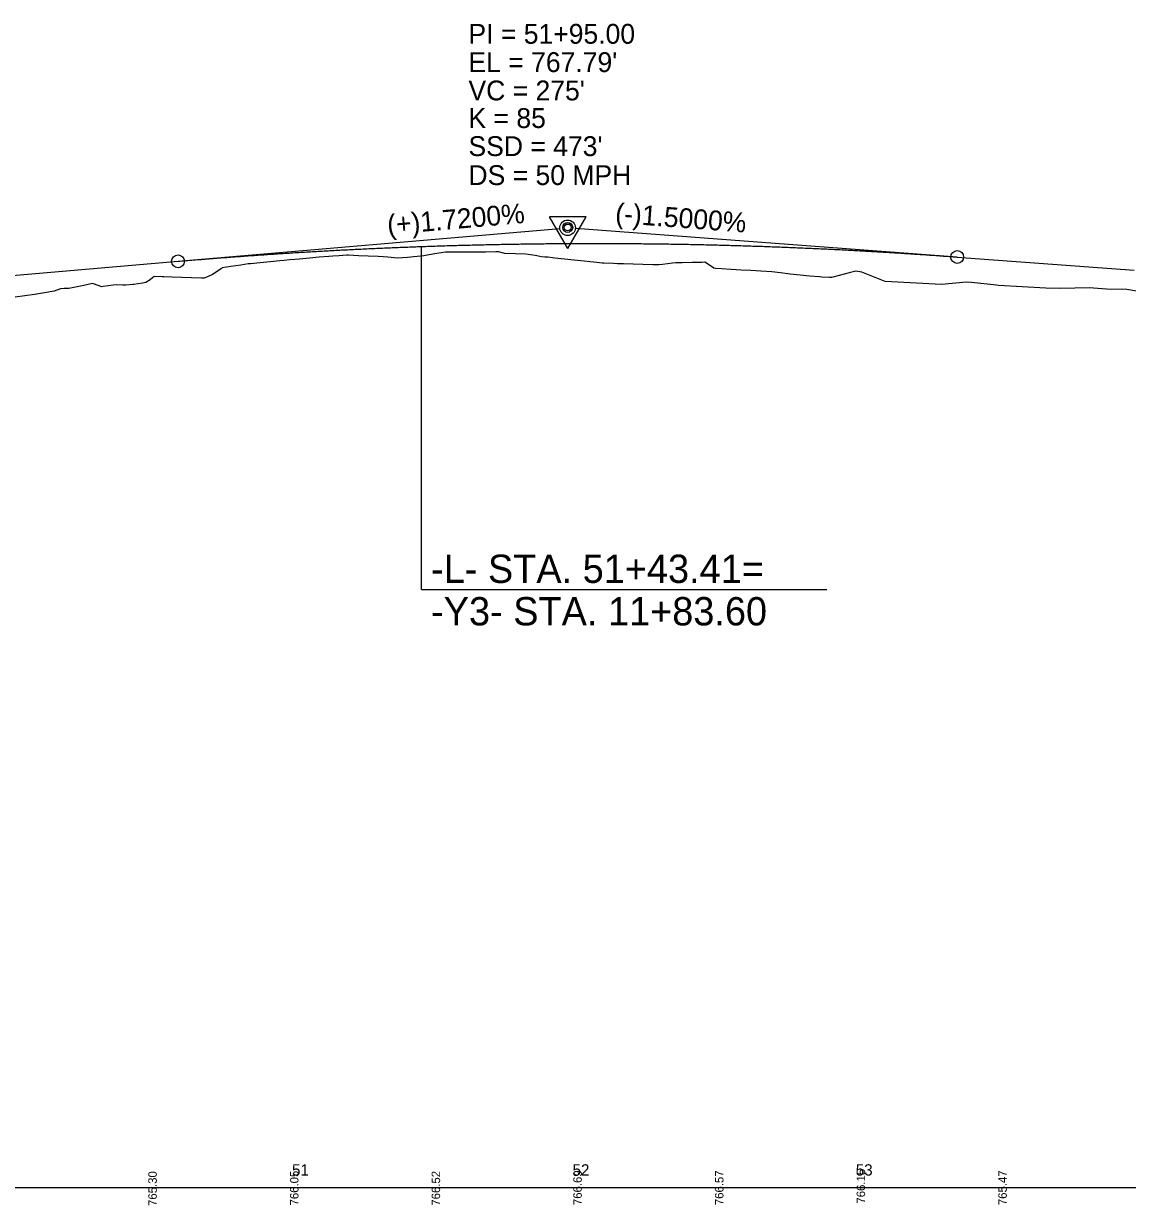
# Model space of a CAD drawing. Extents: x 1554255 to 1803987, y 659549 to 692876.
# Drawn here: x 1558796.7 to 1559186.2, y 692255.6 to 692672.9 of the extents above; entities that cross this region are included whole.
import ezdxf

# ---------------------------------------------------------------- set-up
doc = ezdxf.new("R2010")
doc.units = 0
for name, color, linetype in [('Default', 7, 'Continuous'), ('Exist Profile Cell', 7, 'Continuous'), ('Exist Vertical Profile Ground Line', 7, 'Continuous'), ('Prop PFL Text', 7, 'Continuous'), ('Prop PFL VPI Symbol CELL', 7, 'Continuous'), ('Prop Vertical Profile Curve Label', 7, 'Continuous'), ('Prop Vertical Profile Grade', 7, 'Continuous'), ('Prop Vertical Profile Grade Label', 7, 'Continuous'), ('Prop Vertical Profile Strip Grade', 7, 'Continuous'), ('Prop VPI Label', 7, 'Continuous')]:
    doc.layers.add(name, color=color, linetype=linetype)

msp = doc.modelspace()

# ---------------------------------------------------------------- linework, layer by layer
at = {"layer": 'Exist Profile Cell'}
msp.add_line((1554793.69, 692261.88), (1561762.5, 692261.88), dxfattribs=at)
at = {"layer": 'Exist Vertical Profile Ground Line'}
for p, q in [((1558887.16, 692589.17), (1558883.7, 692588.83)), ((1558888.64, 692589.32), (1558887.16, 692589.17)), ((1558890.62, 692589.5), (1558888.64, 692589.32)), ((1558894.08, 692589.81), (1558890.62, 692589.5)), ((1558897.55, 692590.12), (1558894.08, 692589.81)), ((1558901.01, 692590.43), (1558897.55, 692590.12)), ((1558904.47, 692590.73), (1558901.01, 692590.43)), ((1558905.83, 692590.85), (1558904.47, 692590.73)), ((1558907.94, 692590.98), (1558905.83, 692590.85)), ((1558910.79, 692591.14), (1558907.94, 692590.98)), ((1558911.4, 692591.12), (1558910.79, 692591.14)), ((1558914.86, 692590.97), (1558911.4, 692591.12)), ((1558918.33, 692590.81), (1558914.86, 692590.97)), ((1558921.79, 692590.66), (1558918.33, 692590.81)), ((1558923.59, 692590.58), (1558921.79, 692590.66)), ((1558925.25, 692590.44), (1558923.59, 692590.58)), ((1558928.7, 692590.08), (1558925.25, 692590.44)), ((1558932.18, 692590.4), (1558928.7, 692590.08)), ((1558935.64, 692590.71), (1558932.18, 692590.4)), ((1558937.99, 692590.92), (1558935.64, 692590.71)), ((1558939.11, 692591.12), (1558937.99, 692590.92)), ((1558942.57, 692591.73), (1558939.11, 692591.12)), ((1558945.55, 692592.25), (1558942.57, 692591.73)), ((1558946.03, 692592.25), (1558945.55, 692592.25)), ((1558949.49, 692592.26), (1558946.03, 692592.25)), ((1558952.96, 692592.27), (1558949.49, 692592.26)), ((1558956.42, 692592.27), (1558952.96, 692592.27)), ((1558959.88, 692592.28), (1558956.42, 692592.27)), ((1558963.35, 692592.29), (1558959.88, 692592.28)), ((1558964.32, 692592.29), (1558963.35, 692592.29)), ((1558966.56, 692591.77), (1558964.32, 692592.29)), ((1558970.27, 692591.67), (1558966.56, 692591.77)), ((1558973.97, 692591.57), (1558970.27, 692591.67)), ((1558977.2, 692591.02), (1558973.97, 692591.57)), ((1558979.45, 692590.63), (1558977.2, 692591.02)), ((1558980.66, 692590.52), (1558979.45, 692590.63)), ((1558981.7, 692590.43), (1558980.66, 692590.52)), ((1558984.13, 692590.16), (1558981.7, 692590.43)), ((1558987.59, 692589.78), (1558984.13, 692590.16)), ((1558991.05, 692589.39), (1558987.59, 692589.78)), ((1558994.51, 692589.01), (1558991.05, 692589.39)), ((1558996.55, 692588.79), (1558994.51, 692589.01)), ((1558866.38, 692586.4), (1558863.36, 692584.32)), ((1558866.81, 692586.69), (1558866.38, 692586.4)), ((1558869.84, 692587.15), (1558866.81, 692586.69)), ((1558873.31, 692587.66), (1558869.84, 692587.15)), ((1558875.95, 692588.05), (1558873.31, 692587.66)), ((1558876.77, 692588.14), (1558875.95, 692588.05)), ((1558880.23, 692588.48), (1558876.77, 692588.14)), ((1558883.7, 692588.83), (1558880.23, 692588.48)), ((1558997.98, 692588.64), (1558996.55, 692588.79)), ((1559000.86, 692588.35), (1558997.98, 692588.64)), ((1559001.44, 692588.33), (1559000.86, 692588.35)), ((1559004.9, 692588.21), (1559001.44, 692588.33)), ((1559006.32, 692588.16), (1559004.9, 692588.21)), ((1559008.37, 692588.09), (1559006.32, 692588.16)), ((1559011.83, 692587.98), (1559008.37, 692588.09)), ((1559015.29, 692587.88), (1559011.83, 692587.98)), ((1559018.76, 692587.77), (1559015.29, 692587.88)), ((1559019.55, 692587.75), (1559018.76, 692587.77)), ((1559020.94, 692587.76), (1559019.55, 692587.75)), ((1559022.22, 692587.92), (1559020.94, 692587.76)), ((1559025.68, 692588.33), (1559022.22, 692587.92)), ((1559026.88, 692588.47), (1559025.68, 692588.33)), ((1559029.15, 692588.51), (1559026.88, 692588.47)), ((1559032.61, 692588.57), (1559029.15, 692588.51)), ((1559036.07, 692588.63), (1559032.61, 692588.57)), ((1559037.16, 692588.65), (1559036.07, 692588.63)), ((1559039.53, 692587.11), (1559037.16, 692588.65)), ((1559040.33, 692586.6), (1559039.53, 692587.11)), ((1559040.85, 692586.49), (1559040.33, 692586.6)), ((1559043, 692586.36), (1559040.85, 692586.49)), ((1559046.46, 692586.14), (1559043, 692586.36)), ((1559049.92, 692585.92), (1559046.46, 692586.14)), ((1559053.39, 692585.7), (1559049.92, 692585.92)), ((1559056.85, 692585.49), (1559053.39, 692585.7)), ((1559060.78, 692585.25), (1559056.85, 692585.49)), ((1559063.78, 692584.91), (1559060.78, 692585.25)), ((1559067.24, 692584.51), (1559063.78, 692584.91)), ((1559088.02, 692584.92), (1559084.55, 692584.01)), ((1559090.43, 692585.56), (1559088.02, 692584.92)), ((1559092.56, 692585.22), (1559090.43, 692585.56)), ((1559100.78, 692581.9), (1559092.56, 692585.22)), ((1558821.05, 692581.16), (1558817.9, 692580.51)), ((1558821.36, 692581.05), (1558821.05, 692581.16)), ((1558824.27, 692580.02), (1558821.36, 692581.05)), ((1558829.53, 692580.67), (1558828.29, 692580.52)), ((1558831.75, 692580.61), (1558829.53, 692580.67)), ((1558835.21, 692580.76), (1558832.76, 692580.58)), ((1558835.6, 692580.78), (1558835.21, 692580.76)), ((1558838.68, 692581.28), (1558835.6, 692580.78)), ((1558839.82, 692581.47), (1558838.68, 692581.28)), ((1558841.34, 692582.49), (1558839.82, 692581.47)), ((1558842.14, 692583.14), (1558841.34, 692582.49)), ((1558842.82, 692583.69), (1558842.14, 692583.14)), ((1558845.6, 692583.52), (1558842.82, 692583.69)), ((1558846.15, 692583.49), (1558845.6, 692583.52)), ((1558849.06, 692583.39), (1558846.15, 692583.49)), ((1558852.53, 692583.27), (1558849.06, 692583.39)), ((1558855.99, 692583.16), (1558852.53, 692583.27)), ((1558859.45, 692583.04), (1558855.99, 692583.16)), ((1558860.4, 692583), (1558859.45, 692583.04)), ((1558862.92, 692584.12), (1558860.4, 692583)), ((1558863.36, 692584.32), (1558862.92, 692584.12)), ((1559070.71, 692584.11), (1559067.24, 692584.51)), ((1559074.17, 692583.79), (1559070.71, 692584.11)), ((1559077.63, 692583.47), (1559074.17, 692583.79)), ((1559078.47, 692583.39), (1559077.63, 692583.47)), ((1559081.09, 692583.31), (1559078.47, 692583.39)), ((1559081.82, 692583.29), (1559081.09, 692583.31)), ((1559084.55, 692584.01), (1559081.82, 692583.29)), ((1559120.69, 692580.82), (1559100.78, 692581.9)), ((1559129.44, 692581.6), (1559120.69, 692580.82)), ((1559131.25, 692581.47), (1559129.44, 692581.6)), ((1559140.02, 692580.57), (1559131.25, 692581.47)), ((1558797.12, 692576.82), (1558793.66, 692576.32)), ((1558800.58, 692577.32), (1558797.12, 692576.82)), ((1558804.04, 692577.83), (1558800.58, 692577.32)), ((1558807.51, 692578.42), (1558804.04, 692577.83)), ((1558809.7, 692579.32), (1558807.51, 692578.42)), ((1558810.97, 692579.37), (1558809.7, 692579.32)), ((1558812.64, 692579.43), (1558810.97, 692579.37)), ((1558814.43, 692579.8), (1558812.64, 692579.43)), ((1558817.9, 692580.51), (1558814.43, 692579.8)), ((1558824.82, 692580.09), (1558824.27, 692580.02)), ((1558828.29, 692580.52), (1558824.82, 692580.09)), ((1558832.76, 692580.58), (1558831.75, 692580.61)), ((1559140.82, 692580.47), (1559140.02, 692580.57)), ((1559157.51, 692579.46), (1559140.82, 692580.47)), ((1559162.69, 692579.41), (1559157.51, 692579.46)), ((1559172.78, 692579.63), (1559162.69, 692579.41)), ((1559178.93, 692579.15), (1559172.78, 692579.63)), ((1559186.05, 692579.05), (1559178.93, 692579.15)), ((1559201.63, 692576.3), (1559186.05, 692579.05))]:
    msp.add_line(p, q, dxfattribs=at)
at = {"layer": 'Prop PFL Text'}
for q in [(1558937.1, 692594.33), (1559080.2, 692473.14)]:
    msp.add_line((1558937.1, 692473.14), q, dxfattribs=at)
at = {"layer": 'Prop PFL VPI Symbol CELL'}
for p, q in [((1558988.74, 692593.48), (1558982.24, 692604.68)), ((1558995.19, 692604.68), (1558982.24, 692604.68)), ((1558988.74, 692593.48), (1558995.19, 692604.68))]:
    msp.add_line(p, q, dxfattribs=at)
for radius in [1.75, 1.2]:
    msp.add_circle((1558988.73, 692600.96), radius, dxfattribs=at)
at = {"layer": 'Prop Vertical Profile Curve Label'}
for centre in [(1558851.19, 692589), (1559126.19, 692590.51)]:
    msp.add_circle(centre, 2.25, dxfattribs=at)
at = {"layer": 'Prop Vertical Profile Grade'}
for p, q in [((1558788.69, 692583.63), (1558851.19, 692589)), ((1559126.19, 692590.51), (1559188.69, 692585.83))]:
    msp.add_line(p, q, dxfattribs=at)
msp.add_spline([(1558851.19, 692589), (1558856.69, 692589.47), (1558862.19, 692589.91), (1558867.69, 692590.34), (1558873.19, 692590.75), (1558878.69, 692591.15), (1558884.19, 692591.52), (1558889.69, 692591.88), (1558895.19, 692592.22), (1558900.69, 692592.54), (1558906.19, 692592.85), (1558911.69, 692593.13), (1558917.19, 692593.4), (1558922.69, 692593.65), (1558928.19, 692593.89), (1558933.69, 692594.1), (1558939.19, 692594.3), (1558944.69, 692594.48), (1558950.19, 692594.65), (1558955.69, 692594.79), (1558961.19, 692594.92), (1558966.69, 692595.03), (1558972.19, 692595.12), (1558977.69, 692595.2), (1558983.19, 692595.25), (1558988.69, 692595.29), (1558994.19, 692595.31), (1558999.69, 692595.32), (1559005.19, 692595.3), (1559010.69, 692595.27), (1559016.19, 692595.22), (1559021.69, 692595.16), (1559027.19, 692595.07), (1559032.69, 692594.97), (1559038.19, 692594.85), (1559043.69, 692594.71), (1559049.19, 692594.55), (1559054.69, 692594.38), (1559060.19, 692594.19), (1559065.69, 692593.98), (1559071.19, 692593.75), (1559076.69, 692593.51), (1559082.19, 692593.25), (1559087.69, 692592.97), (1559093.19, 692592.67), (1559098.69, 692592.36), (1559104.19, 692592.02), (1559109.69, 692591.67), (1559115.19, 692591.3), (1559120.69, 692590.92), (1559126.19, 692590.51)], degree=3, dxfattribs=at)
at = {"layer": 'Prop VPI Label'}
for p, q in [((1558851.19, 692589), (1558985.95, 692600.59)), ((1559126.19, 692590.51), (1558991.43, 692600.62))]:
    msp.add_line(p, q, dxfattribs=at)
msp.add_circle((1558988.69, 692600.83), 2.75, dxfattribs=at)

# ---------------------------------------------------------------- texts
at = {"layer": 'Default'}
for s, p in [('51', (1558891.42, 692266.13)), ('52', (1558990.43, 692266.13)), ('53', (1559090.4, 692266.13))]:
    msp.add_text(s, height=4, dxfattribs=at).set_placement(p)
at = {"layer": 'Prop PFL Text'}
for s, p in [('-L- STA. 51+43.41=', (1558940.51, 692475.42)), ('-Y3- STA. 11+83.60', (1558940.51, 692460.42))]:
    msp.add_text(s, height=10, rotation=360, dxfattribs=at).set_placement(p)
at = {"layer": 'Prop Vertical Profile Curve Label'}
for s, p in [("VC = 275'", (1558953.69, 692645.83)), ('K = 85', (1558953.69, 692636.08)), ("SSD = 473'", (1558953.69, 692626.17)), ('DS = 50 MPH', (1558953.69, 692615.93))]:
    msp.add_text(s, height=7, dxfattribs=at).set_placement(p)
at = {"layer": 'Prop Vertical Profile Grade Label'}
for s, rotation, p in [('(+)1.7200%', 4.9153, (1558925.3, 692598.39)), ('(-)1.5000%', 355.7108, (1559005.33, 692602.59))]:
    msp.add_text(s, height=7, rotation=rotation, dxfattribs=at).set_placement(p)
at = {"layer": 'Prop Vertical Profile Strip Grade'}
for s, p in [('766.05', (1558893.69, 692255.58)), ('766.69', (1558993.69, 692255.71)), ('766.57', (1559043.69, 692255.69)), ('766.15', (1559093.69, 692256.24)), ('765.47', (1559143.69, 692255.69)), ('765.30', (1558843.69, 692255.41)), ('766.52', (1558943.69, 692255.49))]:
    msp.add_text(s, height=3, rotation=90, dxfattribs=at).set_placement(p)
at = {"layer": 'Prop VPI Label'}
for s, p in [('PI = 51+95.00', (1558953.69, 692665.83)), ("EL = 767.79'", (1558953.69, 692655.83))]:
    msp.add_text(s, height=7, dxfattribs=at).set_placement(p)

doc.saveas('drawing.dxf')
